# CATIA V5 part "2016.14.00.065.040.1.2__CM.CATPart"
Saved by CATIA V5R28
Part number: 2016.14.00.065.040.1.2__CM
Property "id_number": "2016.14.00.065.040.1.2"
Publications: "Absolute Axis System", "driver", "slider", "base", "cam diagram"
Bounding box of the stored display mesh (mm): x -40 to 145, y -65 to 65, z 0 to 200
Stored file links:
  N:\B2\Normteile\K\2016\11-14\006\cm\2016.14.00.065.040.1.2__CM.CATPart
  H:\CAD_Startmodelle\Tests\fill-in_PRT-SL_TEMPLATE.xlsx
  H:\CAD_Startmodelle\V5-R24\R24_TEMPLATE_PRT_FIBRO_CAM_TECNOLOGIES_INDEX.xlsx
  H:\z_Einordnen\170511__Anfrage_TK_HN\170511__CC01_TKHN.CATPart
  N:\B2\Normteile\K\2016\9xxx\2016.9024.1705.001\Entwurf_\170511__CC01_TKHN.CATPart
  N:\B2\Normteile\K\2016\9xxx\2016.9024.1707.006\Konstruktion\2016.9024.1707.006__HP__CUSTOMIZED_CAM_CM.CATPart
  N:\B2\Normteile\K\2016\9xxx\2016.9024.1707.005\Konstruktion\2016.9024.1707.005__HP__CUSTOMIZED_CAM_CM.CATPart
  N:\B2\Normteile\K\2016\9xxx\2016.9024.1707.008\Konstruktion\2016.9024.1707.008__HP__CUSTOMIZED_CAM_CM.CATPart
  N:\B2\Normteile\K\2016\9xxx\2016.9024.1707.009\Konstruktion\2016.9024.1707.009__HP__CUSTOMIZED_CAM_CM.CATPart
  N:\B2\Normteile\K\2016\9xxx\2016.9024.1707.010\Konstruktion\2016.9024.1707.010__HP__CUSTOMIZED_CAM_CM.CATPart
  N:\B2\Normteile\K\2016\9xxx\2016.9024.1708.002\Konstruktion\2016.9024.1708.002__HP__CUSTOMIZED_CAM_CM.CATPart
  N:\B2\Normteile\K\2016\9xxx\2016.9024.1802.001\Konstruktion\2016.9024.1802.001__HP__CUSTOMIZED_CAM_CM.CATPart
  N:\B2\Normteile\K\2016\9xxx\2016.9024.1802.002\Konstruktion\2016.9024.1802.002__HP__CUSTOMIZED_CAM_CM.CATPart
  N:\B2\Normteile\K\2016\9xxx\2016.9024.1811.003\Konstruktion\2016.9024.1811.003__HP__CUSTOMIZED_CAM_CM.CATPart
  N:\B2\Normteile\K\2016\9xxx\2016.9015.1811.001\Konstruktion\am\2016.9015.1811.001__AM__FCC_HV_DMC_0125-00.CATPart
  N:\B2\Normteile\K\2016\9xxx\2016.9024.1811.009\Konstruktion\2016.9024.1811.009__HP__CUSTOMIZED_CAM_CM.CATPart
  N:\B2\Normteile\K\2016\9xxx\2016.9024.1911.002\Konstruktion\am\2016.9024.1911.002__AM__CUSTOMIZED_CAM_CM.CATPart
  N:\B2\Normteile\K\2016\9xxx\2016.9024.2002.006\Konstruktion\2016.9024.2002.006__AM.CATPart
  N:\B2\Normteile\K\2016\9xxx\2016.9024.2004.001\Konstruktion\2016.9024.2004.001__AM__FCC_HV_CAEC_0260-45.CATPart
  N:\B2\Normteile\K\2016\9xxx\2016.9024.2006.002\Konstruktion\2016.9024.2006.002__AM__FCC_HV_CAEC_0260-40.CATPart
  N:\B2\Normteile\K\2016\9xxx\2016.9024.2006.005\Konstruktion\am\2016.9024.2006.005__AM__CFCC_HV_AEPC_0080-65.CATPart
  N:\B2\Normteile\K\2016\9xxx\2016.9024.2006.004\Konstruktion\am\2016.9024.2006.004__AM__CFCC_HV_AEC_0210-35.CATPart
  N:\B2\Normteile\K\2016\9xxx\2016.9026.2006.001\Konstruktion\am\2016.9026.2006.001__AM__FCC_LV_CAEC_0180-40.CATPart
  N:\B2\Normteile\K\2016\9xxx\2016.9015.2007.001\Konstruktion\am\2016.9015.2007.001__AM__FCC_HV_CDMPC_0090-00.CATPart
  N:\B2\Normteile\K\2016\9xxx\2016.9024.2005.001\Konstruktion\am\2016.9024.2005.001__AM__CFCC_HV_AEPC_1400-70.CATPart
  N:\B2\Normteile\K\2016\9xxx\2016.9024.2007.004\Konstruktion\am\2016.9024.2007.004__AM__CFCC_HV_AEC_1250-80.CATPart
  N:\B2\Normteile\K\2016\11-14\005\2016.11.00.052.040.1.02__AS__DIE_MOUNT_CAM__W52_A0_S40.CATProduct
  N:\B2\Normteile\K\2016\11-14\cm\005\catia\2016.11.00.052.025.1.2__CM.CATPart
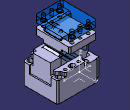
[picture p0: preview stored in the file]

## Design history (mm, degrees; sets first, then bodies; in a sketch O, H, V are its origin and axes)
Parameters
  group "process_parameters"
    modeltype = ""
    stocklist = ""
    id_number = "2016.14.00.065.040.1.2"
    id_number_rough_part = ""
    revision_index = ""
    revision_date = ""
    revision_description = ""
    category = ""
    material = ""
    manufacturing_information = ""
    standard = ""
  group "release_parameters_startmodel"
    sm_revision_index = "2016_00" {design table}
    sm_revision_date = "20.08.2016" {design table}
    sm_revision_name = "Meyer" {design table}
    sm_revision_description = "new part template FIBRO cam tecnologies" {design table}
AxisSystem1: origin (0, 0, 0), X (1, 0, 0), Y (0, 1, 0), Z (0, 0, 1)
Set1 "reference elements"
  Sketch1 "cam diagram" on ZX plane of AxisSystem1, origin (0, 0, 0), H (-1, 0, 0), V (0, 0, 1)
    line L1 (0, 0) -> (40, 0)
    line L2 (40, 0) -> (0, 40)
    point P2 (0, 40)
    line L3 (0, 40) -> (0, 0)
    length L1 = 40
    angle H L2 = 45
    horizontal: L1 H
    coincidence: P2 V
    vertical: L3 V
Body1 "finished_part" (main body)
  Body2 "rough_part"
  Add1 "rough_part": tool Body2
  Body3 "milling operations"
  Remove1 "milling operations": tool Body3
  Body4 "drilling operations"
  Remove2 "drilling operations": tool Body4
Body5 "driver"
  Solid1: solid without history
Body6 "slider"
  Solid2: solid without history
Body7 "base"
  Solid3: solid without history
Body8 "opened position"
  Body9 "slider"
    Body10 "slider"
      Solid4: linked copy from another document
    Assemble1: tool Body10
    Translate1: FirstPoint vertex [element of Sketch1 | element of Sketch1], SecondPoint vertex [element of Sketch1 | element of Sketch1], ToTransfor Assemble1
  Assemble2: tool Body9
  Body11 "driver"
    Body12 "driver"
      Solid5: linked copy from another document
    Assemble3: tool Body12
    Translate2: FirstPoint vertex [element of Sketch1 | element of Sketch1], SecondPoint vertex [element of Sketch1 | element of Sketch1], ToTransfor Assemble3
  Assemble4: tool Body11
